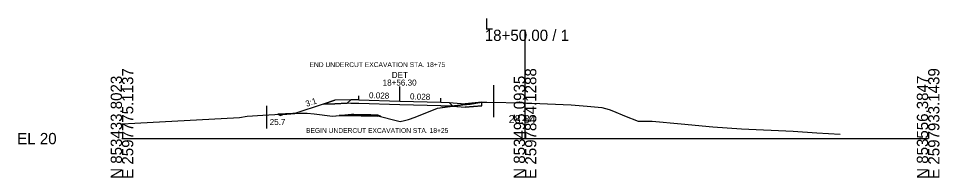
# Model space of a CAD drawing. Extents: x -26 to 1203, y -10 to 9526.
# Drawn here: x -25.7 to 202.8, y 8490.3 to 8529.9 of the extents above; entities that cross this region are included whole.
import ezdxf

# ---------------------------------------------------------------- set-up
doc = ezdxf.new("R2010")
doc.units = 0
for name, color, linetype in [('Exist Cross Section Cell', 7, 'Continuous'), ('Exist XS Center Line Elevation Label', 7, 'Continuous'), ('Exist XS Ground Line', 7, 'Continuous'), ('Prop XS Alignment Label', 7, 'Continuous'), ('Prop XS DDE', 7, 'Continuous'), ('Prop XS DDE Earthwork Shape', 7, 'Continuous'), ('Prop XS DDE Elevations', 7, 'Continuous'), ('Prop XS Earthwork Shape', 7, 'Continuous'), ('Prop XS EOT Tick Mark', 7, 'Continuous'), ('Prop XS Exc Vertical Line 1', 7, 'Continuous'), ('Prop XS Exc Vertical Line 2', 7, 'Continuous'), ('Prop XS Finish Grade', 7, 'Continuous'), ('Prop XS Finish Grade Earthwork', 7, 'Continuous'), ('Prop XS Finish Grade Paved Shoulder', 7, 'Continuous'), ('Prop XS Finish Grade Pavement', 7, 'Continuous'), ('Prop XS Pvmt Edge Slope', 7, 'Continuous'), ('Prop XS SE Text', 7, 'Continuous'), ('Prop XS Side Slope Text', 7, 'Continuous'), ('Prop XS Station Labels', 7, 'Continuous'), ('Prop XS Subgrade Earthwork', 7, 'Continuous'), ('Prop XS Undercut Exc', 7, 'Continuous'), ('Prop XS Undercut Exc Hatch', 7, 'Continuous'), ('Scratch_Level_1', 7, 'Continuous')]:
    doc.layers.add(name, color=color, linetype=linetype)

msp = doc.modelspace()

# ---------------------------------------------------------------- linework, layer by layer
at = {"layer": 'Exist Cross Section Cell'}
for p, q in [((100, 8500), (100, 8527.05)), ((0, 8500), (100, 8500)), ((100, 8500), (200, 8500))]:
    msp.add_line(p, q, dxfattribs=at)
at = {"layer": 'Exist XS Ground Line'}
for p, q in [((78.24, 8507.53), (84.57, 8508.41)), ((84.57, 8508.41), (86.35, 8508.57)), ((86.35, 8508.57), (89.29, 8509.02)), ((89.29, 8509.02), (90.53, 8509.01)), ((90.53, 8509.01), (100, 8508.84)), ((100, 8508.84), (100.32, 8508.83)), ((100.32, 8508.83), (101.65, 8508.77)), ((101.65, 8508.77), (111.42, 8508.35)), ((111.42, 8508.35), (115.38, 8508.05)), ((34.94, 8505.84), (42.35, 8506.21)), ((42.35, 8506.21), (44, 8506.28)), ((44, 8506.28), (45.96, 8506.31)), ((45.96, 8506.31), (47.7, 8506.18)), ((47.7, 8506.18), (52.26, 8505.6)), ((54.09, 8505.76), (56.92, 8506)), ((56.92, 8506), (57.53, 8505.98)), ((72.75, 8505.35), (78.24, 8507.53)), ((115.38, 8508.05), (119.07, 8507.7)), ((119.07, 8507.7), (120.9, 8507.2)), ((120.9, 8507.2), (121.91, 8506.82)), ((121.91, 8506.82), (124.64, 8505.69)), ((0, 8503.63), (3.2, 8503.82)), ((3.2, 8503.82), (29.17, 8505.22)), ((29.17, 8505.22), (31.06, 8505.54)), ((31.06, 8505.54), (34.94, 8505.84)), ((52.26, 8505.6), (54.09, 8505.76)), ((57.53, 8505.98), (63.46, 8505.84)), ((63.46, 8505.84), (64.17, 8505.51)), ((64.17, 8505.51), (67.69, 8504.57)), ((67.69, 8504.57), (69.05, 8504.28)), ((69.05, 8504.28), (70.1, 8504.5)), ((70.1, 8504.5), (71.05, 8504.71)), ((71.05, 8504.71), (72.75, 8505.35)), ((124.64, 8505.69), (128.04, 8504.29)), ((128.04, 8504.29), (130.35, 8504.32)), ((130.35, 8504.32), (131.52, 8504.36)), ((131.52, 8504.36), (138.77, 8503.64)), ((138.77, 8503.64), (146.55, 8502.88)), ((146.55, 8502.88), (153.67, 8502.42)), ((153.67, 8502.42), (166.52, 8501.86)), ((166.52, 8501.86), (172.38, 8501.43)), ((172.38, 8501.43), (178.17, 8501.08))]:
    msp.add_line(p, q, dxfattribs=at)
at = {"layer": 'Prop XS DDE'}
for p, q in [((38.69, 8506.03), (39.35, 8505.7)), ((39.35, 8505.7), (39.92, 8505.99)), ((39.92, 8505.99), (42.92, 8506.24))]:
    msp.add_line(p, q, dxfattribs=at)
at = {"layer": 'Prop XS DDE Earthwork Shape'}
for p, q in [((42.35, 8506.21), (38.69, 8506.03)), ((38.69, 8506.03), (39.35, 8505.7)), ((39.35, 8505.7), (39.92, 8505.99)), ((39.92, 8505.99), (42.9, 8506.23)), ((42.9, 8506.23), (42.35, 8506.21))]:
    msp.add_line(p, q, dxfattribs=at)
at = {"layer": 'Prop XS Earthwork Shape'}
for points in [[(53.86, 8505.74), (54.09, 8505.76), (56.92, 8506), (57.53, 8505.98), (63.46, 8505.84), (64.11, 8505.54), (64.17, 8505.51), (67.69, 8504.57), (69.05, 8504.28), (70.1, 8504.5), (71.05, 8504.71), (72.75, 8505.35), (78.24, 8507.53), (81.87, 8508.03), (81.14, 8508.05), (79.14, 8508.11), (68.96, 8508.39), (58.79, 8508.68), (56.79, 8508.74), (55.9, 8508.76), (52.79, 8508.66), (49.93, 8508.57), (42.92, 8506.23), (44, 8506.28), (45.96, 8506.31), (47.7, 8506.18), (52.26, 8505.6)], [(89.29, 8508.15), (89.29, 8509.02), (86.35, 8508.57), (84.57, 8508.41), (81.87, 8508.03), (82.09, 8508.02), (85.14, 8507.78)], [(53.86, 8505.74), (54.09, 8505.76), (56.92, 8506), (57.53, 8505.98), (63.46, 8505.84), (64.11, 8505.54), (63.79, 8505.54), (59.38, 8505.66)]]:
    msp.add_lwpolyline(points, close=True, dxfattribs=at)
at = {"layer": 'Prop XS EOT Tick Mark'}
for p, q in [((58.79, 8509.6), (58.79, 8510.6)), ((79.14, 8509.02), (79.14, 8510.02))]:
    msp.add_line(p, q, dxfattribs=at)
at = {"layer": 'Prop XS Exc Vertical Line 1'}
msp.add_line((35.84, 8508.12), (35.84, 8502.54), dxfattribs=at)
at = {"layer": 'Prop XS Exc Vertical Line 2'}
msp.add_line((92.21, 8513.3), (92.21, 8505.33), dxfattribs=at)
at = {"layer": 'Prop XS Finish Grade'}
for p, q in [((49.93, 8508.57), (52.79, 8509.53)), ((56.79, 8509.65), (52.79, 8509.53)), ((81.14, 8508.97), (85.14, 8508.65)), ((89.29, 8509.02), (85.14, 8508.65))]:
    msp.add_line(p, q, dxfattribs=at)
at = {"layer": 'Prop XS Finish Grade Earthwork'}
msp.add_line((49.93, 8508.57), (42.92, 8506.23), dxfattribs=at)
at = {"layer": 'Prop XS Finish Grade Paved Shoulder'}
for p, q in [((58.79, 8509.6), (56.79, 8509.65)), ((79.14, 8509.02), (81.14, 8508.97))]:
    msp.add_line(p, q, dxfattribs=at)
at = {"layer": 'Prop XS Finish Grade Pavement'}
for p, q in [((58.79, 8509.6), (68.96, 8509.31)), ((68.96, 8509.31), (79.14, 8509.02))]:
    msp.add_line(p, q, dxfattribs=at)
at = {"layer": 'Prop XS Pvmt Edge Slope'}
for p, q in [((56.79, 8509.65), (55.9, 8508.76)), ((81.14, 8508.97), (82.09, 8508.02))]:
    msp.add_line(p, q, dxfattribs=at)
at = {"layer": 'Prop XS Side Slope Text'}
msp.add_line((68.96, 8509.31), (68.96, 8512.96), dxfattribs=at)
at = {"layer": 'Prop XS Subgrade Earthwork'}
for p, q in [((52.79, 8508.66), (49.93, 8508.57)), ((55.9, 8508.76), (52.79, 8508.66)), ((56.79, 8508.74), (55.9, 8508.76)), ((58.79, 8508.68), (56.79, 8508.74)), ((68.96, 8508.39), (58.79, 8508.68)), ((79.14, 8508.11), (68.96, 8508.39)), ((89.29, 8508.15), (89.29, 8509.02)), ((79.14, 8508.11), (81.14, 8508.05)), ((81.14, 8508.05), (82.09, 8508.02)), ((82.09, 8508.02), (85.14, 8507.78)), ((89.29, 8508.15), (85.14, 8507.78))]:
    msp.add_line(p, q, dxfattribs=at)
at = {"layer": 'Prop XS Undercut Exc'}
for p, q in [((59.38, 8505.66), (53.86, 8505.74)), ((63.79, 8505.54), (59.38, 8505.66)), ((64.11, 8505.54), (63.79, 8505.54))]:
    msp.add_line(p, q, dxfattribs=at)
at = {"layer": 'Prop XS Undercut Exc Hatch'}
for p, q in [((54.75, 8505.81), (54.84, 8505.73)), ((55.11, 8505.72), (55.24, 8505.85)), ((56.06, 8505.92), (56.27, 8505.71)), ((56.5, 8505.7), (56.77, 8505.97)), ((57.41, 8505.98), (57.71, 8505.69)), ((57.9, 8505.68), (58.18, 8505.97)), ((58.86, 8505.95), (59.14, 8505.67)), ((59.29, 8505.66), (59.56, 8505.93)), ((60.3, 8505.92), (60.59, 8505.63)), ((60.67, 8505.63), (60.94, 8505.9)), ((61.75, 8505.88), (62.05, 8505.59)), ((62.04, 8505.59), (62.33, 8505.87)), ((63.2, 8505.85), (63.5, 8505.55)), ((63.42, 8505.55), (63.63, 8505.76))]:
    msp.add_line(p, q, dxfattribs=at)
msp.add_lwpolyline([(63.79, 8505.54), (64.11, 8505.54), (63.46, 8505.84), (61.72, 8505.88), (60.53, 8505.91), (57.53, 8505.98), (57.53, 8505.98), (56.92, 8506), (55.25, 8505.85), (53.86, 8505.74), (59.38, 8505.66)], close=True, dxfattribs=at)
at = {"layer": 'Scratch_Level_1'}
msp.add_lwpolyline([(56.79, 8509.65), (52.79, 8509.53), (49.93, 8508.57), (52.79, 8508.66), (55.9, 8508.76)], close=True, dxfattribs=at)

# ---------------------------------------------------------------- texts
at = {"layer": 'Exist Cross Section Cell'}
for s, p in [('L', (90, 8527.05)), ('18+50.00 / 1', (90, 8524.25)), ('EL 20', (-26, 8498.6))]:
    msp.add_text(s, height=2.8, dxfattribs=at).set_placement(p)
for s, p in [('N 853433.8023', (0, 8490)), ('E 2597775.1137', (2.8, 8490)), ('N 853495.0935', (100, 8490)), ('E 2597854.1288', (102.8, 8490)), ('N 853556.3847', (200, 8490)), ('E 2597933.1439', (202.8, 8490))]:
    msp.add_text(s, height=2.8, rotation=90, dxfattribs=at).set_placement(p)
at = {"layer": 'Exist XS Center Line Elevation Label'}
msp.add_text('28.84', height=2, dxfattribs=at).set_placement((95.93, 8503.84))
at = {"layer": 'Prop XS Alignment Label'}
msp.add_text('DET', height=1.5, dxfattribs=at).set_placement((66.93, 8515.06))
at = {"layer": 'Prop XS DDE Elevations'}
msp.add_text('25.7', height=1.5, dxfattribs=at).set_placement((36.64, 8503.37))
at = {"layer": 'Prop XS SE Text'}
for rotation, p in [(358.3825, (61.27, 8510.03)), (358.385, (71.44, 8509.74))]:
    msp.add_text('0.028', height=1.5, rotation=rotation, dxfattribs=at).set_placement(p)
at = {"layer": 'Prop XS Side Slope Text'}
msp.add_text('3:1', height=1.5, rotation=18.4349, dxfattribs=at).set_placement((45.82, 8507.88))
at = {"layer": 'Prop XS Station Labels'}
msp.add_text('18+56.30', height=1.5, dxfattribs=at).set_placement((64.67, 8513.16))
at = {"layer": 'Prop XS Undercut Exc Hatch'}
for s, p in [('END UNDERCUT EXCAVATION STA. 18+75', (46.52, 8517.77)), ('BEGIN UNDERCUT EXCAVATION STA. 18+25', (45.66, 8501.41))]:
    msp.add_text(s, height=1.2, dxfattribs=at).set_placement(p)

doc.saveas('drawing.dxf')
